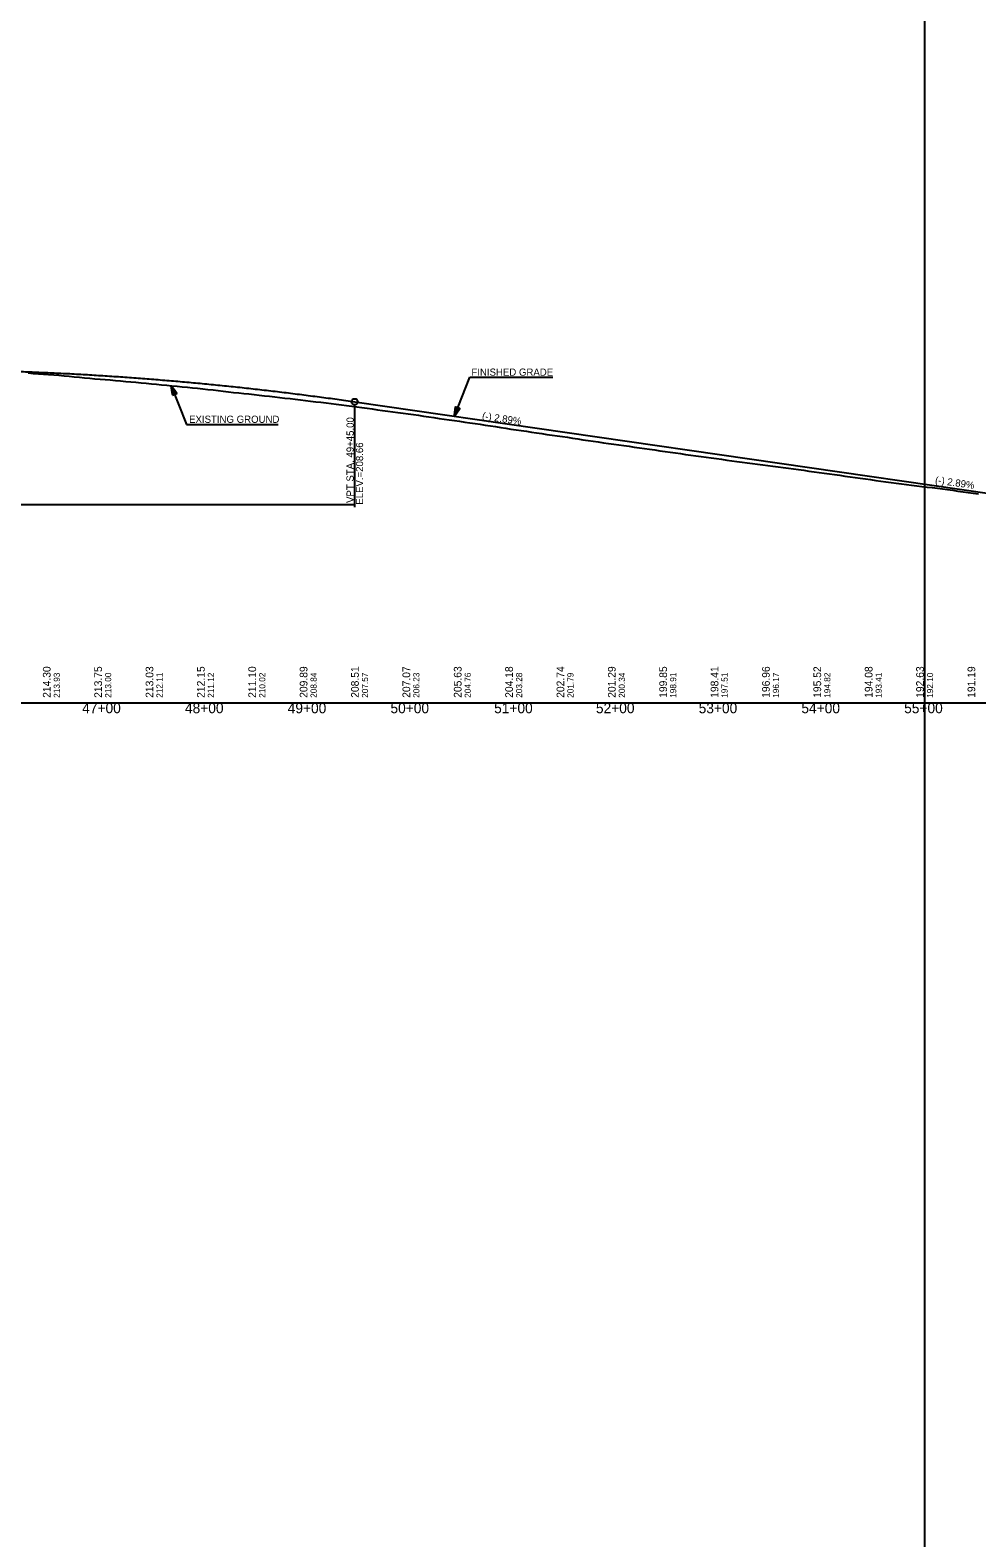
# Model space of a CAD drawing. Extents: x 69 to 2003113, y 512 to 837401.
# Drawn here: x 1892007 to 1892928, y 817195 to 818664 of the extents above; entities that cross this region are included whole.
import ezdxf

# ---------------------------------------------------------------- set-up
doc = ezdxf.new("R2010")
doc.units = 0
for name, color, linetype in [('BR_AUTO DIMENSION', 7, 'Continuous'), ('BR_BORDER LINES', 7, 'Continuous'), ('BR_CENTER LINE BASELINE', 7, 'Continuous'), ('BR_CONCRETE', 7, 'Continuous'), ('BR_GRID DOTS', 7, 'Continuous'), ('BR_GRID LINES', 7, 'Continuous'), ('BR_TEXT', 7, 'Continuous'), ('RD_HC_Points', 7, 'Continuous'), ('RD_PD_ALT1_TrvlWay', 7, 'Continuous'), ('RD_SHT_ID', 7, 'Continuous')]:
    doc.layers.add(name, color=color, linetype=linetype)

msp = doc.modelspace()

# ---------------------------------------------------------------- linework, layer by layer
at = {"layer": 'BR_AUTO DIMENSION'}
msp.add_line((1892877.5, 816758.6), (1892877.5, 820132.3), dxfattribs=at)
at = {"layer": 'BR_BORDER LINES'}
msp.add_line((1889077.5, 818008.6), (1895477.5, 818008.6), dxfattribs=at)
at = {"layer": 'BR_GRID DOTS'}
for p, q in [((1892322.5, 818199.4), (1892322.5, 818298.9)), ((1891462.5, 818201.9), (1892322.5, 818201.9))]:
    msp.add_line(p, q, dxfattribs=at)
msp.add_circle((1892322.5, 818301.9), 3, dxfattribs=at)
at = {"layer": 'BR_GRID LINES'}
msp.add_line((1892322.5, 818301.9), (1892942.5, 818212.4), dxfattribs=at)
msp.add_spline([(1891462.5, 818304.1), (1891479.7, 818306.4), (1891496.9, 818308.7), (1891514.1, 818310.8), (1891531.3, 818312.9), (1891548.5, 818314.9), (1891565.7, 818316.7), (1891582.9, 818318.5), (1891600.1, 818320.1), (1891617.3, 818321.7), (1891634.5, 818323.2), (1891651.7, 818324.6), (1891668.9, 818325.8), (1891686.1, 818327), (1891703.3, 818328.1), (1891720.5, 818329.1), (1891737.7, 818329.9), (1891754.9, 818330.7), (1891772.1, 818331.4), (1891789.3, 818332), (1891806.5, 818332.5), (1891823.7, 818332.9), (1891840.9, 818333.2), (1891858.1, 818333.4), (1891875.3, 818333.5), (1891892.5, 818333.5), (1891909.7, 818333.4), (1891926.9, 818333.2), (1891944.1, 818332.9), (1891961.3, 818332.5), (1891978.5, 818332.1), (1891995.7, 818331.5), (1892012.9, 818330.8), (1892030.1, 818330), (1892047.3, 818329.2), (1892064.5, 818328.2), (1892081.7, 818327.1), (1892098.9, 818326), (1892116.1, 818324.7), (1892133.3, 818323.3), (1892150.5, 818321.9), (1892167.7, 818320.3), (1892184.9, 818318.7), (1892202.1, 818316.9), (1892219.3, 818315.1), (1892236.5, 818313.1), (1892253.7, 818311.1), (1892270.9, 818308.9), (1892288.1, 818306.7), (1892305.3, 818304.4), (1892322.5, 818301.9)], degree=3, dxfattribs=at)
at = {"layer": 'BR_TEXT'}
for points in [[(1892004.6, 818330), (1892009.6, 818329.6), (1892014.6, 818329.3), (1892019.6, 818328.9), (1892024.6, 818328.5), (1892029.6, 818328.1), (1892034.6, 818327.7), (1892039.6, 818327.3), (1892044.6, 818326.8), (1892049.6, 818326.3), (1892054.6, 818325.8), (1892059.6, 818325.4), (1892064.6, 818324.9), (1892069.6, 818324.4), (1892074.6, 818323.9), (1892079.6, 818323.5), (1892084.6, 818323.2), (1892089.6, 818322.8), (1892094.6, 818322.3), (1892099.6, 818321.8), (1892104.6, 818321.3)], [(1892104.6, 818321.3), (1892109.6, 818320.9), (1892114.6, 818320.4), (1892119.6, 818319.9), (1892124.6, 818319.5), (1892129.6, 818319), (1892134.6, 818318.5), (1892139.6, 818318.1), (1892144.6, 818317.6), (1892149.6, 818317.1), (1892154.6, 818316.6), (1892159.6, 818316), (1892164.6, 818315.6), (1892169.6, 818315.1), (1892174.6, 818314.5), (1892179.6, 818314), (1892184.6, 818313.4), (1892189.6, 818312.9), (1892194.6, 818312.3), (1892199.6, 818311.7), (1892204.6, 818311.1), (1892209.6, 818310.6), (1892214.6, 818310), (1892219.6, 818309.6), (1892224.6, 818309.1), (1892229.6, 818308.5), (1892234.6, 818307.8), (1892239.6, 818307.3), (1892244.6, 818306.8), (1892249.6, 818306.2), (1892254.6, 818305.6), (1892259.6, 818305), (1892264.6, 818304.4), (1892269.6, 818303.8), (1892274.6, 818303.2), (1892279.6, 818302.6), (1892284.6, 818302), (1892289.6, 818301.4), (1892294.6, 818300.8), (1892299.6, 818300.2), (1892304.6, 818299.5), (1892309.6, 818298.8), (1892314.6, 818298.2), (1892319.6, 818297.5), (1892324.6, 818296.9), (1892329.6, 818296.2), (1892334.6, 818295.6), (1892339.6, 818294.9), (1892344.6, 818294.2), (1892349.6, 818293.4), (1892354.6, 818292.7), (1892359.6, 818292.2), (1892364.6, 818291.5), (1892369.6, 818290.8), (1892374.6, 818290.2), (1892379.6, 818289.5), (1892384.6, 818288.8), (1892389.6, 818288), (1892394.6, 818287.2), (1892399.6, 818286.5), (1892404.6, 818285.8), (1892409.6, 818285.1), (1892414.6, 818284.4), (1892419.6, 818283.6), (1892424.6, 818282.9), (1892429.6, 818282.1), (1892434.6, 818281.4), (1892439.6, 818280.7), (1892444.6, 818280), (1892449.6, 818279.2), (1892454.6, 818278.4), (1892459.6, 818277.7), (1892464.6, 818276.9), (1892469.6, 818276.2), (1892474.6, 818275.4), (1892479.6, 818274.7), (1892484.6, 818274), (1892489.6, 818273.2), (1892494.6, 818272.4), (1892499.6, 818271.6), (1892504.6, 818270.9), (1892509.6, 818270.2), (1892514.6, 818269.5), (1892519.6, 818268.8), (1892524.6, 818268), (1892529.6, 818267.3), (1892534.6, 818266.5), (1892539.6, 818265.8), (1892544.6, 818265), (1892549.6, 818264.2), (1892554.6, 818263.6), (1892559.6, 818262.9), (1892564.6, 818262.1), (1892569.6, 818261.4), (1892574.6, 818260.7), (1892579.6, 818260.1), (1892584.6, 818259.4), (1892589.6, 818258.6), (1892594.6, 818257.8), (1892599.6, 818257.1), (1892604.6, 818256.4)], [(1892604.6, 818256.4), (1892609.6, 818255.7), (1892614.6, 818255), (1892619.6, 818254.3), (1892624.6, 818253.6), (1892629.6, 818252.9), (1892634.6, 818252.2), (1892639.6, 818251.4), (1892644.6, 818250.7), (1892649.6, 818250), (1892654.6, 818249.4), (1892659.6, 818248.7), (1892664.6, 818248), (1892669.6, 818247.3), (1892674.6, 818246.6), (1892679.6, 818245.9), (1892684.6, 818245.2), (1892689.6, 818244.5), (1892694.6, 818243.9), (1892699.6, 818243.2), (1892704.6, 818242.5), (1892709.6, 818241.9), (1892714.6, 818241.2), (1892719.6, 818240.5), (1892724.6, 818239.9), (1892729.6, 818239.2), (1892734.6, 818238.5), (1892739.6, 818237.9), (1892744.6, 818237.2), (1892749.6, 818236.6), (1892754.6, 818235.9), (1892759.6, 818235.2), (1892764.6, 818234.5), (1892769.6, 818233.8), (1892774.6, 818233.1), (1892779.6, 818232.4), (1892784.6, 818231.7), (1892789.6, 818231), (1892794.6, 818230.3), (1892799.6, 818229.5), (1892804.6, 818228.8), (1892809.6, 818228.1), (1892814.6, 818227.5), (1892819.6, 818226.8), (1892824.6, 818226.1), (1892829.6, 818225.4), (1892834.6, 818224.7), (1892839.6, 818224.1), (1892844.6, 818223.4), (1892849.6, 818222.7), (1892854.6, 818222), (1892859.6, 818221.3), (1892864.6, 818220.7), (1892869.6, 818220.1), (1892874.6, 818219.5), (1892879.6, 818218.9), (1892884.6, 818218.3), (1892889.6, 818217.7), (1892894.6, 818217), (1892899.6, 818216.4), (1892904.6, 818215.7), (1892909.6, 818215), (1892914.6, 818214.3), (1892919.6, 818213.7), (1892924.6, 818213), (1892929.6, 818212.4)]]:
    msp.add_lwpolyline(points, dxfattribs=at)
at = {"layer": 'RD_PD_ALT1_TrvlWay'}
for p, q in [((1892143.9, 818317.6), (1892158.9, 818279.7)), ((1892147.2, 818309.3), (1892143.9, 818317.6)), ((1892143.9, 818317.6), (1892149.3, 818310.1)), ((1892143.9, 818317.6), (1892145.1, 818308.4)), ((1892419.5, 818287.9), (1892434.4, 818325.9)), ((1892434.4, 818325.9), (1892515.2, 818325.9)), ((1892145.1, 818308.4), (1892149.3, 818310.1)), ((1892419.5, 818287.9), (1892420.7, 818297.1)), ((1892419.5, 818287.9), (1892420.7, 818297.1)), ((1892422.8, 818296.3), (1892419.5, 818287.9)), ((1892422.8, 818296.3), (1892419.5, 818287.9)), ((1892419.5, 818287.9), (1892424.9, 818295.5)), ((1892419.5, 818287.9), (1892424.9, 818295.5)), ((1892420.7, 818297.1), (1892424.9, 818295.5)), ((1892420.7, 818297.1), (1892424.9, 818295.5)), ((1892158.9, 818279.7), (1892248.1, 818279.7))]:
    msp.add_line(p, q, dxfattribs=at)
for points in [[(1892147.1, 818309.3), (1892144, 818317.1), (1892147.1, 818309.3), (1892144.1, 818316.8), (1892147, 818309.3), (1892144.2, 818316.5), (1892146.9, 818309.3), (1892144.2, 818316.2), (1892146.8, 818309.2), (1892144.3, 818315.7), (1892146.7, 818309.1), (1892144.3, 818315.1), (1892146.6, 818309.1), (1892144.4, 818314.7), (1892146.5, 818309.1), (1892144.5, 818314.3), (1892146.4, 818309.1), (1892144.5, 818313.9), (1892146.3, 818309), (1892144.6, 818313.5), (1892146.2, 818309), (1892144.6, 818313), (1892146.1, 818308.9), (1892144.7, 818312.4), (1892146, 818308.9), (1892144.7, 818312), (1892145.9, 818308.8), (1892144.8, 818311.4), (1892145.8, 818308.8), (1892144.9, 818310.9), (1892145.7, 818308.7), (1892145, 818310.5), (1892145.6, 818308.7), (1892145, 818310.1), (1892145.5, 818308.6), (1892145.1, 818309.6), (1892145.4, 818308.7), (1892145.2, 818309), (1892145.3, 818308.7)], [(1892144.2, 818317.1), (1892147.2, 818309.4), (1892144.4, 818316.9), (1892147.3, 818309.4), (1892144.5, 818316.6), (1892147.4, 818309.4), (1892144.7, 818316.4), (1892147.5, 818309.5), (1892144.9, 818316.2), (1892147.6, 818309.5), (1892145.1, 818315.9), (1892147.7, 818309.5), (1892145.3, 818315.6), (1892147.7, 818309.5), (1892145.5, 818315.2), (1892147.9, 818309.6), (1892145.7, 818314.9), (1892147.9, 818309.6), (1892146, 818314.6), (1892148, 818309.6), (1892146.2, 818314.3), (1892148.1, 818309.7), (1892146.5, 818313.9), (1892148.2, 818309.8), (1892146.8, 818313.5), (1892148.3, 818309.8), (1892147, 818313.2), (1892148.3, 818309.8), (1892147.3, 818312.8), (1892148.4, 818309.8), (1892147.5, 818312.4), (1892148.5, 818309.9), (1892147.8, 818312.1), (1892148.6, 818310), (1892148, 818311.8), (1892148.7, 818310), (1892148.3, 818311.4), (1892148.8, 818310), (1892148.5, 818311.1), (1892149, 818310), (1892148.7, 818310.9), (1892149.1, 818310.2), (1892149.2, 818310.1), (1892149, 818310.2)], [(1892422.7, 818296.2), (1892419.6, 818288.4), (1892422.6, 818296.3), (1892419.7, 818288.8), (1892422.5, 818296.3), (1892419.7, 818289.1), (1892422.4, 818296.3), (1892419.7, 818289.4), (1892422.4, 818296.4), (1892419.8, 818289.9), (1892422.2, 818296.4), (1892419.9, 818290.4), (1892422.1, 818296.4), (1892420, 818290.8), (1892422, 818296.5), (1892420, 818291.3), (1892421.9, 818296.5), (1892420.1, 818291.7), (1892421.9, 818296.6), (1892420.1, 818292), (1892421.7, 818296.6), (1892420.2, 818292.5), (1892421.6, 818296.6), (1892420.3, 818293.1), (1892421.5, 818296.7), (1892420.3, 818293.5), (1892421.4, 818296.7), (1892420.4, 818294.2), (1892421.3, 818296.7), (1892420.5, 818294.7), (1892421.2, 818296.8), (1892420.5, 818295.1), (1892421.1, 818296.8), (1892420.6, 818295.5), (1892421, 818296.9), (1892420.6, 818296), (1892420.9, 818296.9), (1892420.7, 818296.5), (1892420.8, 818296.9)], [(1892422.7, 818296.2), (1892419.6, 818288.4), (1892422.6, 818296.3), (1892419.7, 818288.8), (1892422.5, 818296.3), (1892419.7, 818289.1), (1892422.4, 818296.3), (1892419.7, 818289.4), (1892422.4, 818296.4), (1892419.8, 818289.9), (1892422.2, 818296.4), (1892419.9, 818290.4), (1892422.1, 818296.4), (1892420, 818290.8), (1892422, 818296.5), (1892420, 818291.3), (1892421.9, 818296.5), (1892420.1, 818291.7), (1892421.9, 818296.6), (1892420.1, 818292), (1892421.7, 818296.6), (1892420.2, 818292.5), (1892421.6, 818296.6), (1892420.3, 818293.1), (1892421.5, 818296.7), (1892420.3, 818293.5), (1892421.4, 818296.7), (1892420.4, 818294.2), (1892421.3, 818296.7), (1892420.5, 818294.7), (1892421.2, 818296.8), (1892420.5, 818295.1), (1892421.1, 818296.8), (1892420.6, 818295.5), (1892421, 818296.9), (1892420.6, 818296), (1892420.9, 818296.9), (1892420.7, 818296.5), (1892420.8, 818296.9)], [(1892419.8, 818288.4), (1892422.8, 818296.2), (1892419.9, 818288.7), (1892422.9, 818296.1), (1892420.1, 818288.9), (1892423, 818296.1), (1892420.3, 818289.1), (1892423, 818296.1), (1892420.5, 818289.4), (1892423.1, 818296.1), (1892420.6, 818289.6), (1892423.2, 818296), (1892420.8, 818289.9), (1892423.3, 818296), (1892421.1, 818290.3), (1892423.4, 818296), (1892421.3, 818290.6), (1892423.5, 818296), (1892421.5, 818291), (1892423.6, 818295.9), (1892421.8, 818291.3), (1892423.7, 818295.9), (1892422, 818291.6), (1892423.7, 818295.8), (1892422.3, 818292.1), (1892423.8, 818295.8), (1892422.6, 818292.3), (1892423.9, 818295.8), (1892422.9, 818292.7), (1892424, 818295.7), (1892423.1, 818293.1), (1892424.1, 818295.7), (1892423.3, 818293.5), (1892424.2, 818295.6), (1892423.6, 818293.7), (1892424.2, 818295.6), (1892423.8, 818294.2), (1892424.4, 818295.6), (1892424, 818294.5), (1892424.5, 818295.5), (1892424.2, 818294.6), (1892424.6, 818295.4), (1892424.7, 818295.4), (1892424.6, 818295.4)], [(1892419.8, 818288.4), (1892422.8, 818296.2), (1892419.9, 818288.7), (1892422.9, 818296.1), (1892420.1, 818288.9), (1892423, 818296.1), (1892420.3, 818289.1), (1892423, 818296.1), (1892420.5, 818289.4), (1892423.1, 818296.1), (1892420.6, 818289.6), (1892423.2, 818296), (1892420.8, 818289.9), (1892423.3, 818296), (1892421.1, 818290.3), (1892423.4, 818296), (1892421.3, 818290.6), (1892423.5, 818296), (1892421.5, 818291), (1892423.6, 818295.9), (1892421.8, 818291.3), (1892423.7, 818295.9), (1892422, 818291.6), (1892423.7, 818295.8), (1892422.3, 818292.1), (1892423.8, 818295.8), (1892422.6, 818292.3), (1892423.9, 818295.8), (1892422.9, 818292.7), (1892424, 818295.7), (1892423.1, 818293.1), (1892424.1, 818295.7), (1892423.3, 818293.5), (1892424.2, 818295.6), (1892423.6, 818293.7), (1892424.2, 818295.6), (1892423.8, 818294.2), (1892424.4, 818295.6), (1892424, 818294.5), (1892424.5, 818295.5), (1892424.2, 818294.6), (1892424.6, 818295.4), (1892424.7, 818295.4), (1892424.6, 818295.4)]]:
    msp.add_lwpolyline(points, dxfattribs=at)

# ---------------------------------------------------------------- texts
at = {"layer": 'BR_CENTER LINE BASELINE'}
for p in [(1892446.1, 818284.9), (1892887.1, 818222.5)]:
    msp.add_text('(-) 2.89%', height=7, rotation=351.7851, dxfattribs=at).set_placement(p)
at = {"layer": 'BR_CONCRETE'}
for s, height, p in [('VPT STA. 49+45.00 ', 7, (1892321.5, 818203.4)), ('ELEV.=208.66', 7, (1892330.7, 818201.7)), ('213.93', 6, (1892035.5, 818013.6)), ('213.00', 6, (1892085.5, 818013.6)), ('212.11', 6, (1892135.5, 818013.6)), ('211.12', 6, (1892185.5, 818013.6)), ('210.02', 6, (1892235.5, 818013.6)), ('208.84', 6, (1892285.5, 818013.6)), ('207.57', 6, (1892335.5, 818013.6)), ('206.23', 6, (1892385.5, 818013.6)), ('204.76', 6, (1892435.5, 818013.6)), ('203.28', 6, (1892485.5, 818013.6)), ('201.79', 6, (1892535.5, 818013.6)), ('200.34', 6, (1892585.5, 818013.6)), ('198.91', 6, (1892635.5, 818013.6)), ('197.51', 6, (1892685.5, 818013.6)), ('196.17', 6, (1892735.5, 818013.6)), ('194.82', 6, (1892785.5, 818013.6)), ('193.41', 6, (1892835.5, 818013.6)), ('192.10', 6, (1892885.5, 818013.6))]:
    msp.add_text(s, height=height, rotation=90, dxfattribs=at).set_placement(p)
at = {"layer": 'RD_HC_Points'}
for s, p in [('214.30', (1892026.5, 818013.6)), ('213.75', (1892076.5, 818013.6)), ('213.03', (1892126.5, 818013.6)), ('212.15', (1892176.5, 818013.6)), ('211.10', (1892226.5, 818013.6)), ('209.89', (1892276.5, 818013.6)), ('208.51', (1892326.5, 818013.6)), ('207.07', (1892376.5, 818013.6)), ('205.63', (1892426.5, 818013.6)), ('204.18', (1892476.5, 818013.6)), ('202.74', (1892526.5, 818013.6)), ('201.29', (1892576.5, 818013.6)), ('199.85', (1892626.5, 818013.6)), ('198.41', (1892676.5, 818013.6)), ('196.96', (1892726.5, 818013.6)), ('195.52', (1892776.5, 818013.6)), ('194.08', (1892826.5, 818013.6)), ('192.63', (1892876.5, 818013.6)), ('191.19', (1892926.5, 818013.6))]:
    msp.add_text(s, height=7.5, rotation=90, dxfattribs=at).set_placement(p)
at = {"layer": 'RD_PD_ALT1_TrvlWay'}
for s, p in [('FINISHED GRADE', (1892436.1, 818327.3)), ('EXISTING GROUND', (1892161.3, 818281.4))]:
    msp.add_text(s, height=7, dxfattribs=at).set_placement(p)
at = {"layer": 'RD_SHT_ID'}
for s, p in [('47+00', (1892057.3, 817998.6)), ('48+00', (1892157.3, 817998.6)), ('49+00', (1892257.3, 817998.6)), ('50+00', (1892357.3, 817998.6)), ('51+00', (1892458.2, 817998.6)), ('52+00', (1892557.3, 817998.6)), ('53+00', (1892657.3, 817998.6)), ('54+00', (1892757.3, 817998.6)), ('55+00', (1892857.3, 817998.6))]:
    msp.add_text(s, height=10, dxfattribs=at).set_placement(p)

doc.saveas('drawing.dxf')
